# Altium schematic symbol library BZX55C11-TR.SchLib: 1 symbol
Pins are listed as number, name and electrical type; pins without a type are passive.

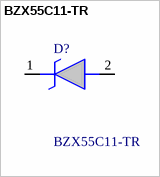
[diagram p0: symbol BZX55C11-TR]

## BZX55C11-TR
designator D?
Vishay BZX55C11-TR Zener Diode, 11V 5% 0.5 W Through Hole 2-Pin DO-35
footprint DIOAD950W60L350D150
pins: 1 K, 2 A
